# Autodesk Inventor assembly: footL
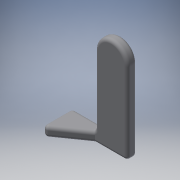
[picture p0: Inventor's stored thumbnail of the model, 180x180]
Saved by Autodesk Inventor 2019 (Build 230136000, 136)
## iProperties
Created: 2020-09
Part Number: footL
Material: 一般
Document SubType Name: Assembly
Designer: kikut
Author: kikut
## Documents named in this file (2)
- F:\openFOAM\basilisk\oversetmeshfootL\CAD\footL.iam
- F:\openFOAM\basilisk\oversetmeshfootL\CAD\footL.ipt
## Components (1 placed, 1 different names)
1. footL:1 — メイト:1, メイト:2
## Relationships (2: Mate 2)
- メイト:1 [Mate]: footL:1
- メイト:2 [Mate]: footL:1
